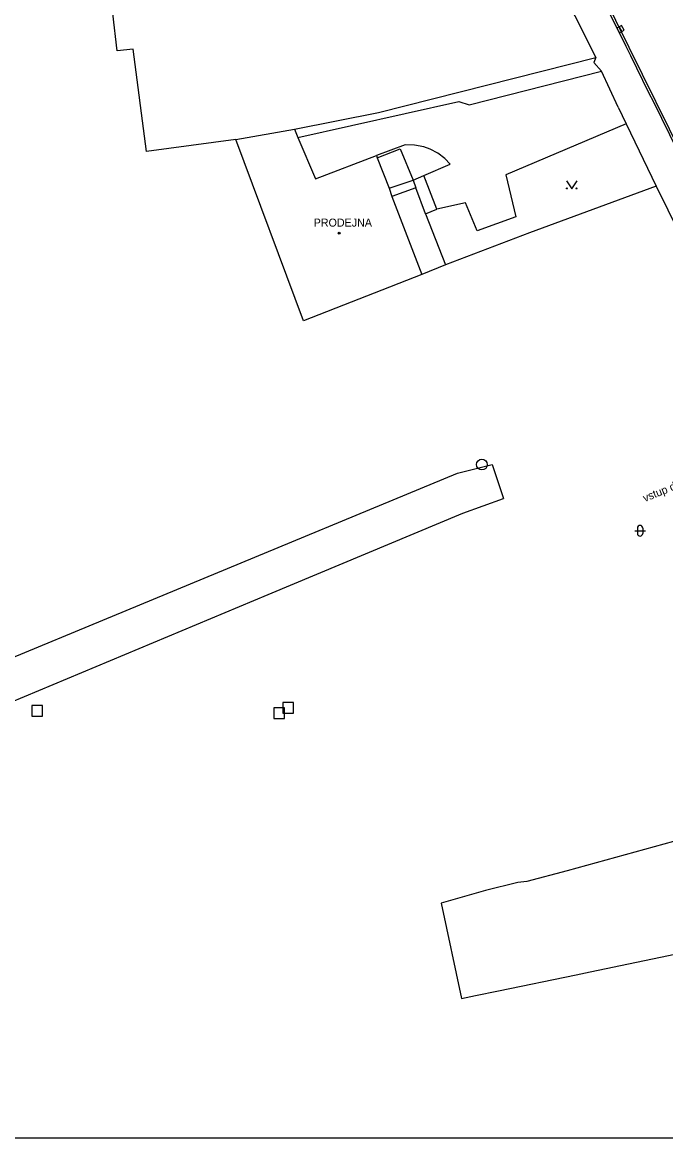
# Model space of a CAD drawing. Extents: x -598341 to -594502, y -1162301 to -1161406.
# Drawn here: x -597906.3 to -597845.9, y -1161730.5 to -1161626 of the extents above; entities that cross this region are included whole.
import ezdxf

# ---------------------------------------------------------------- set-up
doc = ezdxf.new("R2010")
doc.units = 0
for name, color, linetype in [('OKRAJ', 7, 'Continuous'), ('Vrstva 10', 7, 'Continuous'), ('Vrstva 11', 7, 'Continuous'), ('Vrstva 26', 7, 'Continuous'), ('Vrstva 27', 7, 'Continuous'), ('Vrstva 36', 7, 'Continuous'), ('Vrstva 39', 7, 'Continuous'), ('Vrstva 41', 7, 'Continuous'), ('Vrstva 42', 7, 'Continuous'), ('Vrstva 5', 7, 'Continuous'), ('Vrstva 7', 7, 'Continuous'), ('Vrstva 8', 7, 'Continuous')]:
    doc.layers.add(name, color=color, linetype=linetype)

msp = doc.modelspace()

# ---------------------------------------------------------------- linework, layer by layer
at = {"layer": 'OKRAJ'}
msp.add_line((-598126.97, -1161730.49), (-597723.77, -1161730.49), dxfattribs=at)
at = {"layer": 'Vrstva 10'}
msp.add_lwpolyline([(-597853.08, -1161621.32), (-597849.69, -1161628.2), (-597849.25, -1161629.08), (-597847.55, -1161632.54), (-597847.1, -1161633.43), (-597843.33, -1161641.07)], dxfattribs=at)
at = {"layer": 'Vrstva 11'}
for p, q in [((-597870.39, -1161637.46), (-597873.07, -1161638.45)), ((-597868.62, -1161640.33), (-597866.14, -1161639.26)), ((-597871.86, -1161641.51), (-597869.62, -1161640.76)), ((-597869.62, -1161640.76), (-597868.62, -1161640.33)), ((-597869.62, -1161640.76), (-597869.36, -1161641.46)), ((-597867.4, -1161643.46), (-597868.62, -1161640.33)), ((-597869.36, -1161641.46), (-597871.61, -1161642.28)), ((-597868.46, -1161643.92), (-597869.36, -1161641.46)), ((-597868.46, -1161643.92), (-597867.4, -1161643.46)), ((-597868.46, -1161643.92), (-597866.59, -1161648.69))]:
    msp.add_line(p, q, dxfattribs=at)
for points in [[(-597905.87, -1161513.96), (-597893.77, -1161538.4), (-597875.07, -1161576.2), (-597868.12, -1161590.3), (-597858.17, -1161610.48), (-597850.65, -1161625.75), (-597843.12, -1161641.02)], [(-597880.44, -1161636.75), (-597865.33, -1161633.4), (-597864.38, -1161633.69), (-597851.97, -1161630.54)], [(-597849.66, -1161635.48), (-597860.95, -1161640.25), (-597860, -1161644.19), (-597863.61, -1161645.49), (-597864.73, -1161642.89), (-597867.4, -1161643.46)], [(-597872.99, -1161638.67), (-597870.83, -1161637.82), (-597869.62, -1161640.76)], [(-597866.14, -1161639.26), (-597866.64, -1161638.73), (-597867.3, -1161638.23), (-597868.04, -1161637.84), (-597868.63, -1161637.62), (-597869.5, -1161637.47), (-597870.39, -1161637.46)], [(-597915.57, -1161688.96), (-597865.47, -1161668.2), (-597862.21, -1161667.39), (-597861.14, -1161670.6)], [(-597914.17, -1161692.52), (-597883.21, -1161679.58), (-597864.98, -1161671.96), (-597861.14, -1161670.6)]]:
    msp.add_lwpolyline(points, dxfattribs=at)
at = {"layer": 'Vrstva 26'}
for points in [[(-597905.37, -1161690.99), (-597904.37, -1161690.99), (-597904.37, -1161689.99), (-597905.37, -1161689.99)], [(-597881.86, -1161690.7), (-597880.86, -1161690.7), (-597880.86, -1161689.7), (-597881.86, -1161689.7)], [(-597882.68, -1161691.22), (-597881.68, -1161691.22), (-597881.68, -1161690.22), (-597882.68, -1161690.22)]]:
    msp.add_lwpolyline(points, close=True, dxfattribs=at)
at = {"layer": 'Vrstva 27'}
msp.add_line((-597850.31, -1161626.38), (-597850.07, -1161626.82), dxfattribs=at)
msp.add_lwpolyline([(-597850.53, -1161626.5), (-597850.29, -1161626.94), (-597849.85, -1161626.71), (-597850.09, -1161626.26)], close=True, dxfattribs=at)
msp.add_circle((-597863.18, -1161667.41), 0.5, dxfattribs=at)
at = {"layer": 'Vrstva 36'}
for p, q in [((-597848.6, -1161673.36), (-597848.6, -1161673.86)), ((-597848.1, -1161673.36), (-597848.1, -1161673.86)), ((-597848.85, -1161673.61), (-597847.85, -1161673.61))]:
    msp.add_line(p, q, dxfattribs=at)
msp.add_lwpolyline([(-597855.26, -1161640.83), (-597854.76, -1161641.58), (-597854.26, -1161640.83)], dxfattribs=at)
for centre in [(-597855.21, -1161641.53), (-597854.31, -1161641.53)]:
    msp.add_circle(centre, 0.05, dxfattribs=at)
for centre, start, end in [((-597848.35, -1161673.36), 0, 180), ((-597848.35, -1161673.86), 180, 0)]:
    msp.add_arc(centre, 0.25, start, end, dxfattribs=at)
at = {"layer": 'Vrstva 39'}
for radius in [0.09, 0.0398]:
    msp.add_circle((-597876.56, -1161645.73), radius, dxfattribs=at)
at = {"layer": 'Vrstva 5'}
for p, q in [((-597886.24, -1161636.94), (-597880.76, -1161635.98)), ((-597880.76, -1161635.98), (-597880.44, -1161636.75)), ((-597880.44, -1161636.75), (-597878.79, -1161640.62)), ((-597879.9, -1161653.94), (-597886.24, -1161636.94)), ((-597878.79, -1161640.62), (-597873.07, -1161638.45)), ((-597873.07, -1161638.45), (-597872.99, -1161638.67)), ((-597872.99, -1161638.67), (-597871.86, -1161641.51)), ((-597871.86, -1161641.51), (-597871.61, -1161642.28)), ((-597871.61, -1161642.28), (-597868.82, -1161649.6)), ((-597868.82, -1161649.6), (-597879.9, -1161653.94))]:
    msp.add_line(p, q, dxfattribs=at)
at = {"layer": 'Vrstva 7'}
for p, q in [((-597886.24, -1161636.94), (-597894.63, -1161638.08)), ((-597846.84, -1161641.33), (-597833.1, -1161669.29)), ((-597844.31, -1161702.47), (-597855.19, -1161705.47)), ((-597855.19, -1161705.47), (-597858.96, -1161706.48)), ((-597859.82, -1161706.58), (-597862.84, -1161707.32)), ((-597858.96, -1161706.48), (-597859.82, -1161706.58)), ((-597862.84, -1161707.32), (-597866.99, -1161708.51)), ((-597866.99, -1161708.51), (-597865.1, -1161717.45)), ((-597853.03, -1161714.95), (-597837.91, -1161711.81)), ((-597861.62, -1161716.73), (-597854.34, -1161715.22)), ((-597854.34, -1161715.22), (-597853.03, -1161714.95)), ((-597865.1, -1161717.45), (-597863.78, -1161717.18)), ((-597863.78, -1161717.18), (-597861.62, -1161716.73))]:
    msp.add_line(p, q, dxfattribs=at)
for points in [[(-597894.63, -1161638.08), (-597895.87, -1161628.48), (-597897.39, -1161628.65), (-597897.78, -1161625.14), (-597896.15, -1161625.07), (-597897.56, -1161613.77)], [(-597858.4, -1161617.52), (-597852.51, -1161629.25)], [(-597880.76, -1161635.98), (-597872.86, -1161634.41), (-597852.51, -1161629.25)], [(-597852.51, -1161629.25), (-597852.67, -1161629.73), (-597851.97, -1161630.54)], [(-597850.4, -1161633.93), (-597849.66, -1161635.48)], [(-597849.66, -1161635.48), (-597846.84, -1161641.33)], [(-597846.84, -1161641.33), (-597858.73, -1161645.68), (-597866.59, -1161648.69)], [(-597866.59, -1161648.69), (-597868.82, -1161649.6)]]:
    msp.add_lwpolyline(points, dxfattribs=at)
at = {"layer": 'Vrstva 8'}
msp.add_line((-597850.4, -1161633.93), (-597851.97, -1161630.54), dxfattribs=at)

# ---------------------------------------------------------------- texts
at = {"layer": 'Vrstva 41'}
msp.add_text('PRODEJNA', height=0.75, dxfattribs=at).set_placement((-597878.95, -1161645.11))
at = {"layer": 'Vrstva 42'}
msp.add_text('vstup do kolektoru', height=0.7499, rotation=22.1073, dxfattribs=at).set_placement((-597847.9, -1161670.93))

doc.saveas('drawing.dxf')
